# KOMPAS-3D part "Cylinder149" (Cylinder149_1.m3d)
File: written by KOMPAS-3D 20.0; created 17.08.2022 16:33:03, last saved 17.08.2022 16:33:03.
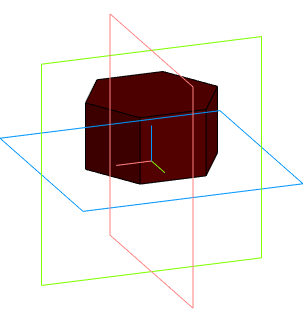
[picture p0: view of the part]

Document properties: Автор: artemsv220@gmail.com; Полное имя файла: \\192.168.2.25\новая общая папка\Медиа\Светильники\Кашпо\Кашпо и вазоны\DWG\Cylinder149_1.m3d

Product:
- Part/product: Cylinder149

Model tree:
1. Операция без истории:1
